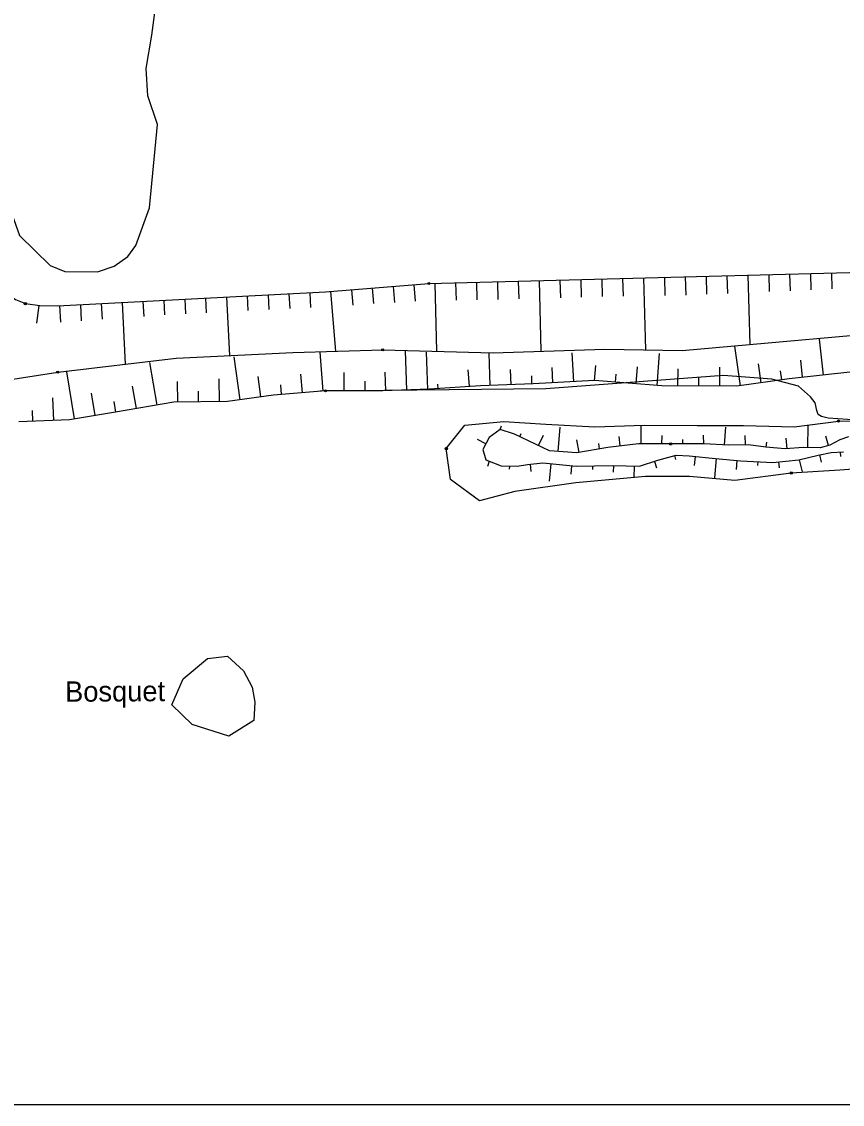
# Model space of a CAD drawing. Extents: x 344013 to 344423, y 298505 to 298795.
# Drawn here: x 344183.1 to 344222.4, y 298504.9 to 298556.7 of the extents above; entities that cross this region are included whole.
import ezdxf

# ---------------------------------------------------------------- set-up
doc = ezdxf.new("R2010")
doc.units = 0
for name, color, linetype in [('Default', 7, 'Continuous'), ('DH_CADRE -CARTOUCHE', 7, 'Continuous'), ('PS_CONST', 7, 'Continuous'), ('TOPO_COURBE NIVEAU', 7, 'Continuous'), ('TOPO_POINT', 7, 'Continuous'), ('TOPO_TALUS-TERRAIN NATUREL', 7, 'Continuous'), ('VOIRIE_ESPACE VERT', 7, 'Continuous')]:
    doc.layers.add(name, color=color, linetype=linetype)

# ---------------------------------------------------------------- blocks, each defined once
blk = doc.blocks.new('POINT_DISPLAY')
at = {"layer": 'Default'}
blk.add_circle((0, 0), 0.05, dxfattribs=at)

msp = doc.modelspace()

# ---------------------------------------------------------------- linework, layer by layer
at = {"layer": 'DH_CADRE -CARTOUCHE'}
msp.add_lwpolyline([(344012.906, 298504.876), (344422.906, 298504.876), (344422.906, 298791.876), (344012.906, 298791.876)], close=True, dxfattribs=at)
at = {"layer": 'TOPO_COURBE NIVEAU'}
for points in [[(344172.229, 298552.34), (344174.81, 298551.459), (344175.417, 298551.545), (344178.101, 298552.1), (344178.967, 298552.397), (344179.598, 298552.428), (344180.464, 298552.159), (344180.902, 298551.719), (344181.319, 298551.048), (344181.616, 298550.278), (344182.963, 298546.5), (344184.44, 298545.064), (344185.14, 298544.773), (344186.698, 298544.755), (344187.508, 298545.028), (344188.162, 298545.491), (344188.533, 298546.018), (344189.189, 298547.821), (344189.573, 298551.818), (344189.112, 298553.182), (344189.034, 298554.487), (344189.312, 298556.099), (344189.48, 298557.412)], [(344222.906, 298537.663), (344222.623, 298537.678), (344221.694, 298537.742), (344221.38, 298537.821), (344221.215, 298537.923), (344221.145, 298538.12), (344221.074, 298538.474), (344220.854, 298538.774), (344220.273, 298539.278), (344218.99, 298539.619), (344216.676, 298539.795), (344208.18, 298539.156), (344197.375, 298539.031)]]:
    msp.add_lwpolyline(points, dxfattribs=at)
at = {"layer": 'TOPO_TALUS-TERRAIN NATUREL'}
for p, q in [((344214.85, 298544.516), (344214.873, 298543.637)), ((344215.85, 298544.542), (344215.873, 298543.68)), ((344216.849, 298544.568), (344216.872, 298543.722)), ((344217.849, 298544.595), (344217.937, 298541.272)), ((344218.849, 298544.621), (344218.87, 298543.806)), ((344219.848, 298544.647), (344219.869, 298543.848)), ((344220.848, 298544.674), (344220.869, 298543.891)), ((344221.848, 298544.7), (344221.868, 298543.933)), ((344200.86, 298544.053), (344200.922, 298543.29)), ((344201.857, 298544.134), (344201.921, 298543.344)), ((344202.854, 298544.2), (344202.94, 298540.951)), ((344203.854, 298544.226), (344203.876, 298543.401)), ((344204.854, 298544.253), (344204.876, 298543.414)), ((344205.853, 298544.279), (344205.876, 298543.431)), ((344206.853, 298544.305), (344206.875, 298543.459)), ((344207.853, 298544.332), (344207.941, 298540.954)), ((344208.852, 298544.358), (344208.874, 298543.516)), ((344209.852, 298544.384), (344209.874, 298543.544)), ((344210.852, 298544.41), (344210.874, 298543.572)), ((344211.851, 298544.437), (344211.874, 298543.587)), ((344212.851, 298544.463), (344212.942, 298541.018)), ((344213.851, 298544.489), (344213.874, 298543.616)), ((344191.878, 298543.495), (344191.914, 298542.796)), ((344192.877, 298543.546), (344193.021, 298540.748)), ((344193.876, 298543.597), (344193.912, 298542.897)), ((344194.874, 298543.648), (344194.91, 298542.947)), ((344195.873, 298543.7), (344195.909, 298542.998)), ((344196.872, 298543.751), (344196.908, 298543.044)), ((344197.87, 298543.809), (344198.103, 298540.954)), ((344198.867, 298543.891), (344198.926, 298543.164)), ((344199.863, 298543.972), (344199.924, 298543.232)), ((344183.888, 298543.149), (344183.781, 298542.298)), ((344184.888, 298543.136), (344184.928, 298542.347)), ((344185.886, 298543.187), (344185.926, 298542.415)), ((344186.885, 298543.239), (344186.924, 298542.483)), ((344187.884, 298543.29), (344188.035, 298540.336)), ((344188.882, 298543.341), (344188.919, 298542.619)), ((344189.881, 298543.392), (344189.917, 298542.688)), ((344190.88, 298543.443), (344190.915, 298542.746)), ((344221.466, 298539.812), (344221.282, 298541.53)), ((344197.518, 298539.042), (344197.367, 298540.91)), ((344201.518, 298539.089), (344201.449, 298540.969)), ((344202.517, 298539.126), (344202.452, 298540.911)), ((344209.509, 298539.49), (344209.437, 298540.871)), ((344217.499, 298539.297), (344217.223, 298541.19)), ((344189.556, 298538.374), (344189.209, 298540.409)), ((344193.539, 298538.629), (344193.255, 298540.682)), ((344205.512, 298539.309), (344205.453, 298540.838)), ((344213.5, 298539.31), (344213.619, 298540.848)), ((344220.471, 298539.705), (344220.384, 298540.519)), ((344185.611, 298537.708), (344185.234, 298539.961)), ((344196.521, 298538.962), (344196.449, 298539.847)), ((344198.518, 298539.05), (344198.519, 298539.939)), ((344200.518, 298539.052), (344200.485, 298539.943)), ((344204.514, 298539.255), (344204.46, 298540.059)), ((344206.512, 298539.348), (344206.484, 298540.074)), ((344208.51, 298539.438), (344208.472, 298540.165)), ((344210.508, 298539.541), (344210.564, 298540.268)), ((344211.505, 298539.464), (344211.535, 298539.848)), ((344212.503, 298539.387), (344212.565, 298540.197)), ((344214.5, 298539.288), (344214.504, 298540.102)), ((344216.5, 298539.276), (344216.506, 298540.182)), ((344218.488, 298539.441), (344218.358, 298540.34)), ((344219.478, 298539.585), (344219.416, 298540.012)), ((344190.545, 298538.514), (344190.531, 298539.494)), ((344192.545, 298538.541), (344192.53, 298539.632)), ((344194.53, 298538.766), (344194.395, 298539.741)), ((344195.524, 298538.881), (344195.486, 298539.347)), ((344199.518, 298539.048), (344199.519, 298539.517)), ((344203.016, 298539.157), (344203.002, 298539.369)), ((344207.511, 298539.387), (344207.496, 298539.77)), ((344215.5, 298539.282), (344215.502, 298539.711)), ((344186.597, 298537.873), (344186.418, 298538.943)), ((344188.57, 298538.206), (344188.387, 298539.277)), ((344191.545, 298538.527), (344191.538, 298539.044)), ((344184.614, 298537.636), (344184.567, 298538.717)), ((344187.584, 298538.038), (344187.497, 298538.546)), ((344183.615, 298537.592), (344183.593, 298538.105)), ((344205.986, 298537.2), (344206.045, 298537.383)), ((344208.771, 298536.148), (344208.862, 298537.309)), ((344212.735, 298536.521), (344212.741, 298537.373)), ((344216.734, 298536.463), (344216.786, 298537.318)), ((344220.721, 298536.338), (344220.744, 298537.4)), ((344206.925, 298536.86), (344206.999, 298537.015)), ((344207.828, 298536.43), (344208.066, 298536.928)), ((344211.741, 298536.414), (344211.687, 298536.86)), ((344213.735, 298536.513), (344213.738, 298536.918)), ((344214.735, 298536.515), (344214.734, 298536.729)), ((344215.736, 298536.523), (344215.732, 298536.929)), ((344217.734, 298536.463), (344217.727, 298536.915)), ((344219.723, 298536.281), (344219.684, 298536.782)), ((344221.705, 298536.441), (344221.58, 298536.877)), ((344205.3, 298536.51), (344204.9, 298536.716)), ((344209.767, 298536.096), (344209.659, 298536.701)), ((344210.751, 298536.271), (344210.705, 298536.53)), ((344218.728, 298536.359), (344218.75, 298536.596)), ((344214.334, 298535.952), (344214.385, 298535.77)), ((344215.329, 298535.911), (344215.282, 298535.472)), ((344216.323, 298535.805), (344216.249, 298534.879)), ((344217.32, 298535.725), (344217.285, 298535.286)), ((344220.311, 298535.756), (344220.456, 298535.167)), ((344221.283, 298535.993), (344221.353, 298535.645)), ((344222.271, 298536.121), (344222.279, 298535.913)), ((344205.467, 298535.679), (344205.373, 298535.433)), ((344206.427, 298535.452), (344206.424, 298535.298)), ((344207.419, 298535.541), (344207.453, 298535.183)), ((344208.415, 298535.563), (344208.335, 298534.725)), ((344209.411, 298535.468), (344209.373, 298535.07)), ((344210.41, 298535.463), (344210.413, 298535.293)), ((344211.41, 298535.483), (344211.399, 298535.161)), ((344212.41, 298535.45), (344212.391, 298534.9)), ((344213.373, 298535.677), (344213.472, 298535.37)), ((344218.319, 298535.663), (344218.308, 298535.476)), ((344219.316, 298535.65), (344219.346, 298535.363))]:
    msp.add_line(p, q, dxfattribs=at)
for points in [[(344159.089, 298561.039), (344159.354, 298561.091), (344159.742, 298561.084), (344160.297, 298560.96), (344160.706, 298560.777), (344161.231, 298560.46), (344172.069, 298553.135), (344173.202, 298552.277), (344176.155, 298549.708), (344180.474, 298545.354), (344182.152, 298543.854), (344182.779, 298543.428), (344183.25, 298543.23), (344183.942, 298543.143), (344184.794, 298543.131), (344197.63, 298543.79), (344202.568, 298544.192), (344226.369, 298544.819)], [(344154.898, 298538.173), (344172.574, 298538.285), (344178.724, 298539.008), (344184.798, 298539.951), (344190.475, 298540.627), (344196.057, 298540.894), (344200.363, 298541.02), (344205.66, 298540.877), (344210.998, 298541.058), (344214.704, 298540.981), (344226.887, 298542.078), (344234.332, 298542.806), (344240.181, 298542.741), (344244.62, 298541.963), (344249.438, 298542.301), (344254.988, 298542.441), (344260.239, 298542.252), (344263.443, 298542.475), (344268.331, 298542.177), (344273.659, 298541.766), (344276.981, 298541.619), (344282.364, 298541.26)], [(344222.868, 298539.962), (344219.829, 298539.636), (344217.32, 298539.271), (344213.732, 298539.292), (344210.498, 298539.542), (344207.568, 298539.389), (344205.042, 298539.291), (344202.608, 298539.129), (344200.363, 298539.047), (344197.624, 298539.051), (344195.137, 298538.85), (344192.938, 298538.546), (344190.365, 298538.512), (344187.569, 298538.035), (344185.371, 298537.668), (344182.931, 298537.563)], [(344222.906, 298535.302), (344222.254, 298535.262), (344219.93, 298535.117), (344217.231, 298534.766), (344215.049, 298534.951), (344212.947, 298534.947), (344209.617, 298534.646), (344206.688, 298534.226), (344204.994, 298533.78), (344203.602, 298534.812), (344203.408, 298536.285), (344204.291, 298537.416), (344206.156, 298537.578), (344208.172, 298537.465), (344210.518, 298537.335), (344212.878, 298537.41), (344215.427, 298537.39), (344217.64, 298537.395), (344220.073, 298537.335), (344222.19, 298537.607), (344222.906, 298537.611)], [(344222.672, 298536.843), (344222.248, 298536.702), (344221.767, 298536.459), (344221.303, 298536.326), (344220.516, 298536.343), (344219.627, 298536.273), (344218.705, 298536.361), (344217.879, 298536.465), (344216.934, 298536.451), (344215.746, 298536.523), (344214.155, 298536.51), (344212.619, 298536.521), (344211.146, 298536.342), (344209.665, 298536.077), (344208.351, 298536.181), (344206.675, 298536.979), (344205.983, 298537.201), (344205.462, 298536.824), (344205.162, 298536.242), (344205.295, 298535.745), (344206.034, 298535.461), (344206.804, 298535.444), (344207.301, 298535.53), (344208.033, 298535.6), (344209.63, 298535.447), (344211.386, 298535.484), (344212.653, 298535.442), (344213.543, 298535.732), (344214.417, 298535.975), (344215.03, 298535.943), (344216.298, 298535.807), (344217.51, 298535.709), (344219.045, 298535.621), (344220.295, 298535.752), (344221.216, 298535.979), (344221.831, 298536.104), (344222.436, 298536.127)]]:
    msp.add_lwpolyline(points, dxfattribs=at)
at = {"layer": 'VOIRIE_ESPACE VERT'}
msp.add_lwpolyline([(344192.99, 298522.516), (344191.236, 298523.078), (344190.268, 298524.016), (344190.806, 298525.259), (344191.965, 298526.225), (344192.924, 298526.35), (344193.702, 298525.648), (344194.117, 298524.853), (344194.235, 298524.136), (344194.193, 298523.263), (344192.99, 298522.516)], dxfattribs=at)

# ---------------------------------------------------------------- block references
at = {"layer": 'TOPO_POINT'}
for p in [(344202.568, 298544.192), (344183.25, 298543.23), (344200.363, 298541.02), (344184.798, 298539.951), (344197.624, 298539.051), (344222.19, 298537.607), (344203.408, 298536.285), (344214.155, 298536.51), (344219.93, 298535.117)]:
    msp.add_blockref('POINT_DISPLAY', p, dxfattribs=at)

# ---------------------------------------------------------------- texts
at = {"layer": 'PS_CONST'}
msp.add_text('Bosquet', height=0.9758, rotation=0.3665, dxfattribs=at).set_placement((344185.156, 298524.158))

doc.saveas('drawing.dxf')
